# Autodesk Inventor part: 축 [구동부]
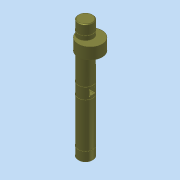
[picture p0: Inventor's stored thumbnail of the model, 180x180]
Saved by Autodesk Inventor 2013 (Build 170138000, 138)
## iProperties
Company: 한국ATC센터
Created: 2015-04
Part Number: 축 [구동부]
Document SubType Name: Modeling
Designer: KYOUNG IL JANG
Density: 1 g/cm^3
Material: 일반
Mass: 77.3127 g
Surface Area: 163.755 cm^2
Volume: 77.3127 cm^3
Author: KYOUNG IL JANG
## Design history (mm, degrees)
sketch "스케치1"
  geometry: C1 r 11 at (0, 0); 1 further point
  constraints: 1 centre point, 1 coincident
  dimensions: "d0" = 22 diameter of C1
extrude "돌출1" new body sketch "스케치1" stored distance "d1" = 180; taper "d2" = 0 deg
sketch "스케치2"
  geometry: L1 (-10.247, -4)-(10.247, -4); L2 (-10.247, 4)-(10.247, 4); A1 r 11 centre (0, 0) between (-10.247, -4) and (10.247, -4) reference; 1 further point
  constraints: 4 end point, 4 point on circle, 2 parallel, 1 horizontal
  dimensions: "d3" = 8 distance between parallel lines of L2 L1
extrude "돌출2" cut sketch "스케치2" stored distance "d4" = 8; taper "d5" = 0 deg
sketch "스케치3"
  geometry: 5 further points
hole "구멍1" sketch "스케치3" at (-4, 4), (4, 4), (4, -4), (-4, -4) diameter "d6" = 2; stored, may be unused: countersink angle "d10" = 90 deg, drill point angle "d12" = 118 deg; dims "d7" = 6, "d8" = 4, "d9" = 2, "d11" = 8
chamfer "모따기1" distance "d13" = 1; stored, may be unused: second distance "d14" = 2, angle "d15" = 45 deg
sketch "스케치4"
  geometry: L1 (-10, 9)-(-11, 9); L2 (-11, 9)-(-11, 7.8); L3 (-11, 7.8)-(-10, 7.8); L4 (-10, 7.8)-(-10, 9); L5 (-10, 90)-(10, 90) reference; L6 (0, -15)-(0, 90) reference; L7 (-10, 74.8)-(-11, 74.8); L8 (-11, 74.8)-(-11, 76); L9 (-11, 76)-(-10, 76); L10 (-10, 76)-(-10, 74.8); 1 further point
  constraints: 16 end point, 4 parallel, 2 equal length, 2 horizontal, 2 perpendicular, 1 collinear
  dimensions: "d16" = 7.8 distance from line of L3 point (0, 0); "d17" = 82.2 distance between parallel lines of L3 L5 (derived); "d18" = 11 distance from line of point (0, 0) L2; "d19" = 1 distance of L2.end L3.end; "d20" = 1.2 distance of L1.end L2.end; "d27" = 14 distance between parallel lines of L5 L9
revolve "회전1" sketch "스케치4" stored, may be unused: angle "d21" = 90 deg
sketch "스케치5"
  geometry: L1 (11, 52)-(-7, 52); L2 (-7, 52)-(-7, 69); L3 (-7, 69)-(11, 69); L4 (11, 69)-(11, 52); 1 further point
  constraints: 8 end point, 2 parallel, 1 horizontal, 1 perpendicular
  dimensions: "d22" = 17 distance of L3.end L1.start; "d23" = 36 diameter of L4 L2; "d24" = 7 horizontal distance of L2.end point (0, 0); "d25" = 52 distance from line of L1 point (0, 0)
revolve "회전2" sketch "스케치5" stored, may be unused: angle "d26" = 90 deg
node "솔리드1"
mirror "대칭1"
mirror "대칭2"
